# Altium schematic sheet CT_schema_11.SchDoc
size 147 x 119 mm
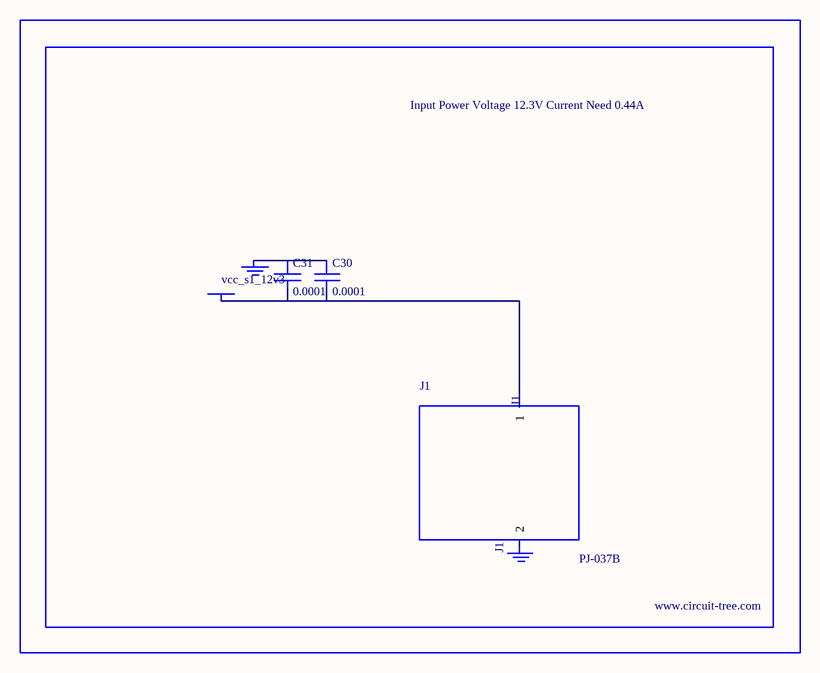
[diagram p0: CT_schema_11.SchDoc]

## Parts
BORDER10  (no value)
C30  0.0001  [EXV-9H]
C31  0.0001  [EXV-9H]
GND_INSTANCE_10_0  (no value)
GND_INSTANCE_10_1  (no value)
J1  PJ-037B  [PJ-037B_PACKAGE]
POWER_INSTANCE_10_0  vcc_s1_12v3

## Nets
NetC30_1: C30.1 C31.1 GND_INSTANCE_10_0.0(GND)
NetC30_2: C30.2 C31.2 J1.1 POWER_INSTANCE_10_0.0(PWR)

Not connected (* = marked no-connect by the designer): GND_INSTANCE_10_1 0(GND); J1 2

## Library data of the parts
BORDER10 = BORDER_PAGE10
C30 C31 = EDK107M035A9HAA
GND_INSTANCE_10_0 GND_INSTANCE_10_1 = GND
POWER_INSTANCE_10_0 = PWR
